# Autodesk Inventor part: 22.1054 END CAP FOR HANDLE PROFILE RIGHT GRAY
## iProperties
Created: 2007-01
Part Number: 22.1054 END CAP FOR HANDLE PROFILE RIGHT GRAY
Document SubType Name: Modeling
Designer: Andy Moles
Material: ABS Plastic
Density: 1.06 g/cm^3
Mass: 4.21262 g
Surface Area: 32.835 cm^2
Volume: 3.97417 cm^3
Author: Andy Moles
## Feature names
1. Base1
